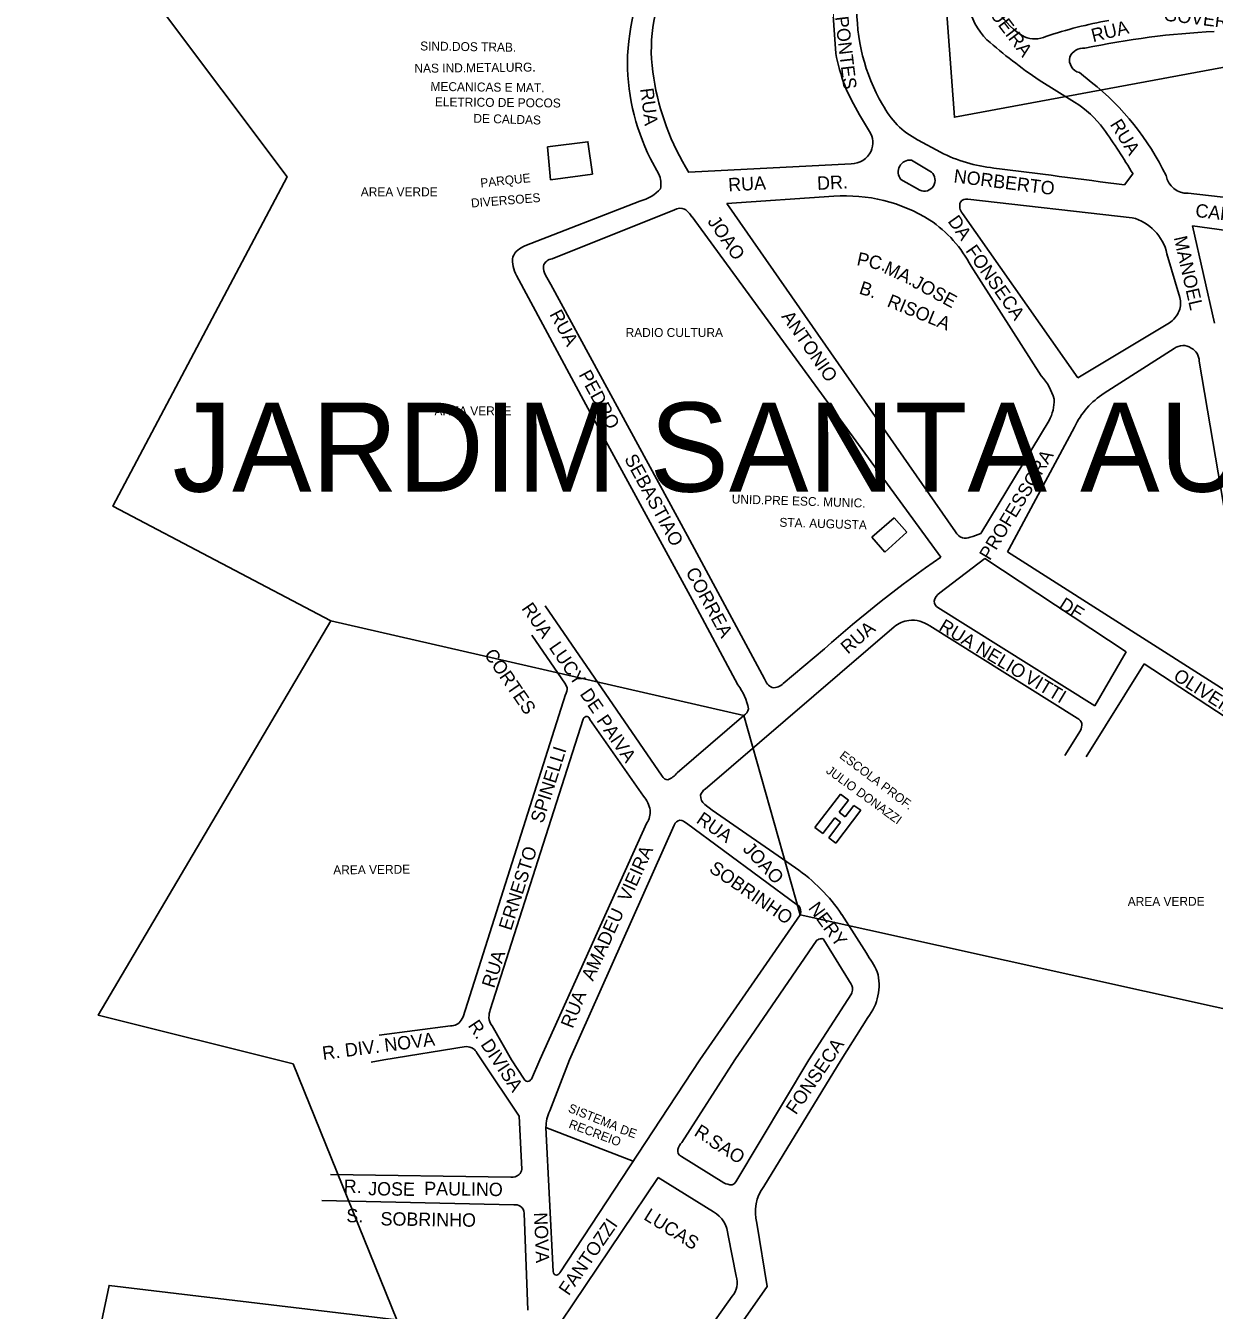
# Model space of a CAD drawing. Extents: x 325709 to 364434, y 7573432 to 7597073.
# Drawn here: x 336886 to 337419, y 7588890 to 7589466 of the extents above; entities that cross this region are included whole.
import ezdxf

# ---------------------------------------------------------------- set-up
doc = ezdxf.new("R2010")
doc.units = 0
for name, color, linetype in [('EDIFEXISTENT', 7, 'Continuous'), ('EDIFIDENTIF', 7, 'Continuous'), ('EDIFOBRAEXIS', 7, 'Continuous'), ('LIMITE_BAIRROS_MUNICIPIOS', 7, 'Continuous'), ('LOGRADOURO', 7, 'Continuous'), ('LOGRADOURO_TEXTO', 7, 'Continuous')]:
    doc.layers.add(name, color=color, linetype=linetype)

msp = doc.modelspace()

# ---------------------------------------------------------------- linework, layer by layer
at = {"layer": 'EDIFEXISTENT'}
for p, q in [((337265.78, 7589236.42), (337275.74, 7589245.1)), ((337275.74, 7589245.1), (337281.44, 7589238.7)), ((337281.44, 7589238.7), (337271.63, 7589229.75)), ((337271.63, 7589229.75), (337265.78, 7589236.42)), ((337240.24, 7589106.18), (337251.67, 7589121.15)), ((337255.26, 7589118.4), (337251.13, 7589113)), ((337251.67, 7589121.15), (337255.26, 7589118.4)), ((337260.86, 7589113.91), (337249.59, 7589099.16)), ((337251.13, 7589113), (337253.77, 7589110.98)), ((337253.77, 7589110.98), (337257.68, 7589116.11)), ((337257.68, 7589116.11), (337260.86, 7589113.91)), ((337243.82, 7589103.45), (337240.24, 7589106.18)), ((337249.18, 7589110.46), (337243.82, 7589103.45)), ((337246.41, 7589101.59), (337251.71, 7589108.53)), ((337251.71, 7589108.53), (337249.18, 7589110.46)), ((337249.59, 7589099.16), (337246.41, 7589101.59))]:
    msp.add_line(p, q, dxfattribs=at)
at = {"layer": 'EDIFOBRAEXIS'}
for p, q in [((337121.63, 7589396.76), (337120.22, 7589411.58)), ((337283.54, 7589405.5), (337292.48, 7589400.18)), ((337287.29, 7589392), (337278.78, 7589396.89)), ((337119.58, 7588971.61), (337158.7, 7588956.44))]:
    msp.add_line(p, q, dxfattribs=at)
msp.add_lwpolyline([(337120.22, 7589411.58), (337138.37, 7589413.8), (337140.39, 7589399.28), (337121.63, 7589396.76)], dxfattribs=at)
for centre, radius, start, end in [((337282.9, 7589400.24), 5.31, 83.02404, 219.11617), ((337289.21, 7589396.52), 4.91, 247.05944, 48.15887)]:
    msp.add_arc(centre, radius, start, end, dxfattribs=at)
at = {"layer": 'LIMITE_BAIRROS_MUNICIPIOS'}
for points in [[(337769.02, 7588985.15), (337839.73, 7589261.51), (337695.54, 7589265.36), (337682.83, 7589413.05), (337659.48, 7589402.1), (337608.62, 7589481.66), (337302.83, 7589424.81), (337289.17, 7589608.02), (336886.18, 7589554.25), (337003.47, 7589398.07), (336925.28, 7589250.26), (337023.13, 7589198.92)], [(336888.36, 7588603.3), (337027.12, 7588760.98), (336904.2, 7588808.66), (336923.62, 7588900.77), (337052.69, 7588885.28), (337006.14, 7589000.16), (336918.76, 7589021.97), (337023.13, 7589198.92), (337208.32, 7589156.4), (337233.63, 7589066.99), (337574.29, 7588991.44)]]:
    msp.add_lwpolyline(points, dxfattribs=at)
at = {"layer": 'LOGRADOURO'}
for p, q in [((337247.36, 7589484.89), (337249.61, 7589453.38)), ((337340.86, 7589441.47), (337356.74, 7589431.57)), ((337364.19, 7589440.54), (337358.86, 7589444.83)), ((337260.3, 7589425.93), (337264.65, 7589418.4)), ((337296.56, 7589409.08), (337286.62, 7589414.51)), ((337166.5, 7589406.17), (337170.17, 7589399.25)), ((337256.43, 7589403.91), (337183.7, 7589400.07)), ((337382.92, 7589399.38), (337379.17, 7589394.4)), ((337200.67, 7589386.08), (337248.7, 7589389.31)), ((337527.51, 7589376.67), (337407.74, 7589390.73)), ((337110.12, 7589367.07), (337161.74, 7589387.2)), ((337122.36, 7589361.24), (337177.27, 7589383.32)), ((337303.3, 7589238.83), (337200.67, 7589386.08)), ((337308.85, 7589388.04), (337382.52, 7589379.72)), ((337185.09, 7589380.1), (337296.67, 7589227.45)), ((337358.18, 7589307.94), (337306.39, 7589381.61)), ((337409.56, 7589376.03), (337512.37, 7589362.39)), ((337419.46, 7589332.41), (337409.56, 7589376.03)), ((337398.11, 7589363.56), (337403.92, 7589343.98)), ((337310.27, 7589357.98), (337341.78, 7589308.79)), ((337399.22, 7589332.51), (337358.18, 7589307.94)), ((337370, 7589300.98), (337401.45, 7589321.01)), ((337412.65, 7589315.37), (337426.09, 7589236.32)), ((337345.28, 7589288.73), (337314.66, 7589238.11)), ((337467.83, 7589139.72), (337326.66, 7589229.83)), ((337296.23, 7589211.37), (337316.45, 7589226.86)), ((337316.45, 7589226.86), (337379.85, 7589184.94)), ((337171.71, 7589129.22), (337119.24, 7589205.58)), ((337365.82, 7589160.77), (337295.41, 7589204.8)), ((337190.98, 7589123.44), (337275.81, 7589196.18)), ((337291.72, 7589196.63), (337357.91, 7589155.25)), ((337379.85, 7589184.94), (337365.82, 7589160.77)), ((337361.95, 7589137.88), (337387.89, 7589179.55)), ((337387.89, 7589179.55), (337462.64, 7589130.7)), ((337094.6, 7589024.43), (337136.28, 7589154.82)), ((337139.22, 7589154.67), (337163.29, 7589120.23)), ((337208.32, 7589156.4), (337178.38, 7589130.73)), ((337359.38, 7589149.66), (337352.34, 7589138.46)), ((337164.85, 7589108.2), (337116.85, 7589001.91)), ((337130.12, 7589001.91), (337177.15, 7589107.28)), ((337182.58, 7589108.06), (337232.46, 7589071.36)), ((337263.32, 7589049.77), (337252.35, 7589067.07)), ((337204.31, 7589001.91), (337241.05, 7589055.59)), ((337244.3, 7589055.72), (337256.47, 7589035.83)), ((337256.6, 7589031.49), (337237.53, 7589001.91)), ((337251.96, 7589001.91), (337263.93, 7589020.87)), ((337076.75, 7589017.14), (337044.77, 7589013.02)), ((337104.12, 7589001.91), (337095.45, 7589017.15)), ((337046.85, 7589001.91), (337083.78, 7589007.95)), ((337088.61, 7589005.16), (337090.68, 7589001.91)), ((337046.85, 7589001.91), (337041.18, 7589000.9)), ((337109.74, 7588993.25), (337104.12, 7589001.91)), ((337116.85, 7589001.91), (337113.04, 7588993.32)), ((337121.31, 7588979.11), (337130.12, 7589001.91)), ((337188.58, 7589001.91), (337125.73, 7588906.33)), ((337180.56, 7588964.89), (337204.31, 7589001.91)), ((337217.26, 7588945.18), (337251.96, 7589001.91)), ((337122.81, 7588907), (337119.58, 7588971.61)), ((337199.34, 7588946.76), (337180.37, 7588958.59)), ((337103.8, 7588949.25), (337022.89, 7588950.45)), ((337120.16, 7588875.23), (337169.98, 7588949.12)), ((337169.98, 7588949.12), (337194.68, 7588933.83)), ((337105.15, 7588936.9), (337018.98, 7588938.9)), ((337111.51, 7588889.59), (337109.77, 7588933.13)), ((337201.27, 7588923.09), (337204.9, 7588904.97)), ((337203.08, 7588895.9), (337165.78, 7588843.39))]:
    msp.add_line(p, q, dxfattribs=at)
for points in [[(337217.62, 7589172.87), (337183.02, 7589236.98), (337121.82, 7589349.69), (337119.39, 7589353.99)], [(337205.63, 7589170.13), (337185.11, 7589208.43), (337137.45, 7589295.93), (337106.4, 7589353.78)], [(337326.66, 7589229.83), (337327.4, 7589231.2), (337356.67, 7589285.79)], [(337113.24, 7589192.5), (337128.39, 7589170.45), (337129.09, 7589168.88)], [(337244.56, 7589186.35), (337244.56, 7589186.35), (337225.99, 7589170.82)], [(337128.37, 7589165.76), (337082.38, 7589021.22), (337081.53, 7589019.68)], [(337231.53, 7589088.05), (337194.1, 7589113.94), (337190.89, 7589116.52)], [(337233.79, 7589069.4), (337233.94, 7589068.23), (337233.63, 7589066.99), (337188.58, 7589001.91)], [(337090.68, 7589001.91), (337107.58, 7588976.61), (337108.7, 7588952.89)], [(337237.53, 7589001.91), (337204.7, 7588947.27), (337203.96, 7588946.34), (337203.05, 7588945.89)], [(337095.77, 7588723.03), (337133.29, 7588777.9), (337218.81, 7588900.32), (337214.1, 7588928.71)]]:
    msp.add_lwpolyline(points, dxfattribs=at)
for centre, radius, start, end in [((337287.19, 7589443.98), 131.25, 153.80676, 176.26166), ((337241.49, 7589455.03), 74.66, 154.73756, 189.75124), ((337350.75, 7589489.58), 33.15, 185.01757, 240.06536), ((337343.84, 7589473.18), 84.8, 178.21055, 210.22456), ((337339.35, 7589481.37), 30.96, 191.12934, 224.88516), ((337408.22, 7589268.06), 203.4, 100.23039, 108.44114), ((337460.21, 7589620.72), 215.35, 228.46497, 236.34384), ((337338.87, 7589471.95), 12.04, 247.23376, 294.585), ((337436.84, 7589101.73), 361.95, 92.76329, 102.03915), ((337252.63, 7589449.6), 96.46, 178.2585, 206.76302), ((337325, 7589466.93), 76.6, 190.19357, 212.36417), ((337360.37, 7589450.59), 5.96, 168.3095, 255.33954), ((337360.68, 7589448.99), 6.76, 84.3469, 155.47256), ((337279.8, 7589460.03), 113.28, 188.96366, 211.96064), ((337289.56, 7589346.44), 120.1, 25.75032, 51.58255), ((337303.08, 7589447.08), 36.49, 207.03429, 242.57288), ((337330.87, 7589390.47), 48.57, 36.8322, 57.8123), ((337257.29, 7589413.34), 8.93, 335.1622, 34.46098), ((337086.81, 7589220.53), 345.93, 31.1307, 35.12789), ((337302.8, 7589446.55), 35.9, 242.56718, 243.19991), ((337256.43, 7589413.81), 9.91, 270.02732, 334.79029), ((337327.6, 7589470.15), 68.51, 243.05462, 264.08438), ((336236.06, 7580811.98), 8658.21, 82.41331, 82.80453), ((337160.08, 7589394.74), 11.06, 349.52672, 24.08143), ((337407.15, 7589400.28), 9.56, 189.98392, 273.49902), ((337157.56, 7589404.59), 17.88, 283.51444, 318.46235), ((337254.06, 7589318.56), 70.95, 57.89895, 94.33144), ((337179.83, 7589378.61), 5.36, 68.60928, 118.57139), ((337173.04, 7589372.03), 14.5, 33.81386, 52.91698), ((337310.85, 7589385.05), 5.64, 162.57924, 217.59317), ((337308.19, 7589384.73), 3.37, 78.60104, 143.52071), ((337260.35, 7589331.94), 56.31, 27.54599, 56.09044), ((337377.27, 7589359.05), 21.33, 12.20768, 75.74096), ((337113.32, 7589358.15), 9.48, 109.74489, 155.09746), ((337117.45, 7589360.34), 12.85, 171.97354, 210.72747), ((337122.82, 7589356.68), 4.58, 95.76086, 162.75783), ((337125.91, 7589357.64), 7.47, 176.89188, 209.21858), ((337394.8, 7589341.35), 9.49, 338.60223, 16.03887), ((337391.58, 7589343.29), 13.21, 305.35074, 335.89479), ((337405.43, 7589315.94), 6.44, 55.44812, 128.15048), ((337405.66, 7589315.15), 7, 1.84938, 60.72325), ((337324.32, 7589292.51), 23.87, 13.99891, 43.00371), ((337329.29, 7589297.45), 18.21, 331.39102, 2.61058), ((337389.55, 7589270.37), 36.32, 122.56967, 154.8744), ((337307.79, 7589240.83), 4.92, 204.05192, 254.23402), ((337307.79, 7589240.23), 4.35, 252.11242, 298.38298), ((337305.8, 7589255.49), 19.5, 281.99025, 296.99902), ((337611.48, 7588774.77), 551.38, 124.81698, 131.71728), ((337299.11, 7589206.66), 5.52, 121.42369, 169.89743), ((337297.7, 7589208.16), 4.06, 187.46666, 235.67829), ((337283.94, 7589186.6), 12.56, 97.16408, 130.29746), ((337283.85, 7589185.58), 13.56, 54.5551, 96.27449), ((337185.4, 7589154.73), 25.42, 10.65698, 37.26877), ((337224.12, 7589175.09), 6.87, 198.84637, 244.11998), ((337221.71, 7589174.59), 5.71, 264.0938, 318.66117), ((337122.02, 7589168.88), 7.08, 333.81529, 359.94891), ((337206.43, 7589159.91), 3.98, 298.23843, 353.13586), ((337138.07, 7589154.05), 1.95, 89.50377, 156.91609), ((337136.99, 7589153.91), 2.36, 18.8471, 62.31071), ((337356.01, 7589151.51), 4.2, 18.00242, 63.10287), ((337349.04, 7589153.35), 10.97, 340.35739, 357.14747), ((337174.15, 7589130.27), 2.66, 203.2015, 271.78964), ((337171.3, 7589135.82), 8.72, 289.64013, 324.29598), ((337194.75, 7589118.51), 6.21, 127.44196, 160.22105), ((337154.34, 7589112.04), 12.13, 8.80476, 42.44253), ((337193.67, 7589120.39), 4.77, 177.35265, 234.33317), ((337156.51, 7589113.4), 9.82, 328.05731, 2.92398), ((337180.3, 7589106.14), 3.35, 101.21246, 160.0738), ((337179.27, 7589104.77), 4.66, 44.85269, 85.44931), ((337186.48, 7589022.53), 79.51, 34.06453, 55.48753), ((337231.36, 7589069.17), 2.45, 5.29747, 63.1957), ((337243.56, 7589051.64), 4.68, 96.47354, 122.43312), ((337243.36, 7589055.32), 1.02, 23.17956, 108.73444), ((337186.49, 7588998.75), 92.23, 27.59845, 33.58685), ((337245.57, 7589035.45), 23.44, 321.57093, 14.89712), ((337253.44, 7589033.78), 3.66, 0.17242, 33.94862), ((337252.32, 7589033.61), 4.78, 333.63774, 2.18839), ((337076.78, 7589022.86), 5.72, 269.73045, 326.17495), ((337104.24, 7589020.97), 10.25, 160.28126, 179.93393), ((337099.45, 7589020.86), 5.46, 178.64953, 222.78762), ((337082.83, 7588999.16), 8.84, 61.69242, 83.82992), ((337077.02, 7588996.43), 14.51, 36.9731, 46.41432), ((337111.86, 7588994.65), 2.54, 213.49526, 257.80028), ((337110.83, 7588994.76), 2.64, 280.80605, 326.96622), ((337137.02, 7588971.55), 17.43, 154.29473, 179.78972), ((337185.13, 7588960.07), 6.64, 133.50541, 165.19705), ((337181.42, 7588961.16), 2.78, 167.37946, 247.70312), ((337104.15, 7588954.22), 4.98, 266.00877, 312.61319), ((337105.53, 7588953.02), 3.17, 308.82249, 357.5275), ((337202.89, 7588953.6), 7.7, 242.50023, 271.12769), ((337233.47, 7588933.53), 19.96, 144.29231, 193.97178), ((337105.62, 7588931.6), 5.33, 62.84294, 95.06427), ((337105.6, 7588932.96), 4.17, 2.31402, 54.02405), ((337188.3, 7588922.52), 12.98, 2.51651, 60.5886), ((337124.41, 7588906.89), 1.6, 175.94292, 266.73188), ((337122.74, 7588908.88), 3.93, 293.75287, 319.43511), ((337196.05, 7588902.02), 9.33, 318.94933, 18.41138)]:
    msp.add_arc(centre, radius, start, end, dxfattribs=at)

# ---------------------------------------------------------------- texts
at = {"layer": 'EDIFIDENTIF'}
for s, rotation, p in [('SIND.DOS TRAB.', 359.16693, (337063.12, 7589454.77)), ('NAS IND.METALURG.', 0.61612, (337060.59, 7589444.72)), ('MECANICAS E MAT.', 359.31146, (337067.76, 7589436.62)), ('ELETRICO DE POCOS', 359.44545, (337069.73, 7589429.69)), ('DE CALDAS', 358.45327, (337086.97, 7589422.33)), ('PARQUE', 6.08793, (337090.35, 7589393.27)), ('AREA VERDE', 359.97973, (337036.51, 7589389.33)), ('DIVERSOES', 4.6909, (337086.12, 7589384.26)), ('AREA VERDE', 0.14375, (337069.57, 7589291.01)), ('UNID.PRE ESC. MUNIC.', 358.19436, (337202.87, 7589251.56)), ('STA. AUGUSTA', 358.22485, (337224.25, 7589241.11)), ('ESCOLA PROF.', 322.98856, (337250.9, 7589137.66)), ('JULIO DONAZZI', 323.97815, (337244.88, 7589130.94)), ('AREA VERDE', 0.50356, (337024.18, 7589085.15)), ('AREA VERDE', 0.15722, (337380.57, 7589070.97)), ('SISTEMA', 338.31591, (337129.2, 7588978.73)), ('RECREIO', 339.36416, (337129.49, 7588971.59)), ('DE', 340.44411, (337152.43, 7588969.16))]:
    msp.add_text(s, height=4, rotation=rotation, dxfattribs=at).set_placement(p)
msp.add_text('RADIO CULTURA', height=4, dxfattribs=at).set_placement((337155.3, 7589326.22))
at = {"layer": 'LIMITE_BAIRROS_MUNICIPIOS'}
msp.add_text('JARDIM SANTA AUGUSTA', height=40, dxfattribs=at).set_placement((336952.04, 7589256.82))
at = {"layer": 'LOGRADOURO_TEXTO'}
for s, rotation, p in [('JUNQUEIRA', 307.37051, (337305.3, 7589488.14)), ('PONTES', 276.76859, (337249.23, 7589469.79)), ('GOVERNADOR', 353.1123, (337396.38, 7589468.19)), ('RUA', 13.77755, (337365.01, 7589458.43)), ('RUA', 277.1728, (337161.83, 7589437.56)), ('RUA', 301.62555, (337372.4, 7589421.61)), ('NORBERTO', 352.78494, (337302.25, 7589395.56)), ('RUA', 3.02024, (337201.48, 7589391.5)), ('DR.', 3.02024, (337241.35, 7589392.16)), ('CARLOS', 353.30642, (337410.66, 7589380.11)), ('JOAO', 304.87429, (337191.82, 7589377.99)), ('DA', 305.11098, (337299.58, 7589378.14)), ('MANOEL', 282.78146, (337401.18, 7589370.82)), ('FONSECA', 305.11098, (337307.57, 7589364.91)), ('PC.', 347.98446, (337258.67, 7589358.52)), ('MA.', 335.58141, (337270.71, 7589355.05)), ('B.', 342.09791, (337259.67, 7589345.76)), ('JOSE', 331.56407, (337283.32, 7589348.96)), ('RISOLA', 337.92887, (337272.18, 7589340.07)), ('RUA', 298.30868, (337121.01, 7589336.42)), ('ANTONIO', 304.87429, (337224.98, 7589335.37)), ('PEDRO', 298.50134, (337134.09, 7589309.34)), ('SEBASTIAO', 298.50134, (337154.55, 7589271.67)), ('PROFESSORA', 58.8312, (337318.69, 7589225.62)), ('CORREA', 298.34992, (337182.07, 7589220.9)), ('RUA', 304.49292, (337108.41, 7589204.44)), ('DE', 327.45093, (337349.17, 7589204.71)), ('RUA', 328.97092, (337295.39, 7589194.92)), ('RUA', 40.69146, (337255, 7589183.68)), ('LUCY', 304.49292, (337120.69, 7589186.92)), ('NELIO', 328.97092, (337311.92, 7589184.91)), ('CORTES', 304.49292, (337091.58, 7589183.8)), ('VITTI', 328.97092, (337333.79, 7589171.76)), ('OLIVEIRA', 327.45093, (337400.57, 7589172.8)), ('DE', 304.49292, (337134.55, 7589166.03)), ('PAIVA', 304.49292, (337142.06, 7589154.19)), ('SPINELLI', 72.35019, (337118.2, 7589107.74)), ('RUA', 325.33447, (337186.59, 7589108.62)), ('ERNESTO', 72.35019, (337103.94, 7589059.61)), ('VIEIRA', 65.69709, (337156.99, 7589072.39)), ('JOAO', 313.08293, (337207.53, 7589096.22)), ('SOBRINHO', 325.44736, (337192.35, 7589086.62)), ('NERY', 306.37733, (337237.02, 7589069.99)), ('AMADEU', 65.69709, (337140.65, 7589036.95)), ('RUA', 72.35019, (337096.32, 7589033.79)), ('RUA', 68.41213, (337131.56, 7589015.69)), ('R. DIVISA', 303.74795, (337084.33, 7589017.35)), ('R. DIV. NOVA', 7.34581, (337019.62, 7589001.91)), ('FONSECA', 55.60346, (337231.69, 7588976.96)), ('R.', 328.04501, (337185.63, 7588968.29)), ('SAO', 328.04501, (337191.97, 7588963.9)), ('R.', 359.14703, (337028.81, 7588942.25)), ('JOSE', 359.14703, (337039.79, 7588941.2)), ('PAULINO', 359.14703, (337064.94, 7588941.31)), ('S.', 359.14703, (337029.99, 7588929.12)), ('SOBRINHO', 359.14703, (337045.34, 7588927.68)), ('LUCAS', 328.04501, (337163.03, 7588930.62)), ('NOVA', 272.29344, (337114.21, 7588933.43)), ('FANTOZZI', 55.30753, (337129.76, 7588895.83))]:
    msp.add_text(s, height=6, rotation=rotation, dxfattribs=at).set_placement(p)

doc.saveas('drawing.dxf')
